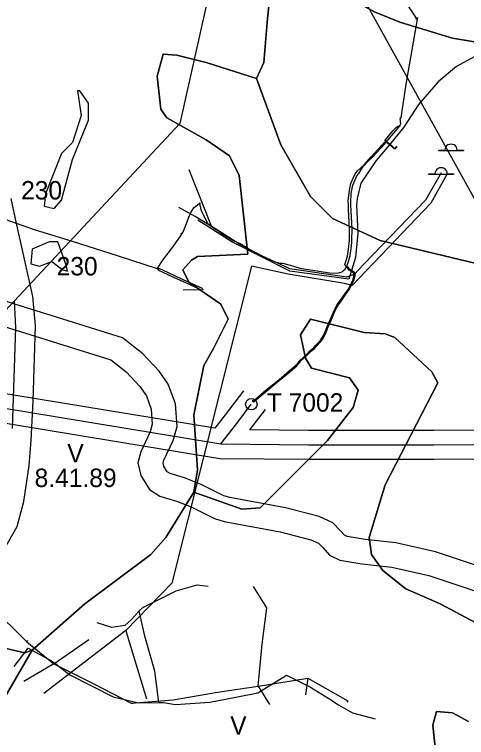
# Model space of a CAD drawing. Extents: x -694504 to -690518, y -983661 to -978958.
# Drawn here: x -691746 to -691377, y -981663 to -981074 of the extents above; entities that cross this region are included whole.
import ezdxf

# ---------------------------------------------------------------- set-up
doc = ezdxf.new("R2010")
doc.units = 0
for name, color, linetype in [('BPEJ', 7, 'Continuous'), ('kabelové a venkovní rozvody telefonu', 7, 'Continuous'), ('lokální biokoridory', 7, 'Continuous'), ('ochranné pásmo dálkového kabelu', 7, 'Continuous'), ('ochranné pásmo radioreleové trasy', 7, 'Continuous'), ('ochranné pásmo silnic', 7, 'Continuous'), ('ochranné pásmo vedení', 7, 'Continuous'), ('trafostanice', 7, 'Continuous'), ('třídy přednosti v ochraně ZP', 7, 'Continuous'), ('vedení NN', 7, 'Continuous'), ('vedení VN 35kV', 7, 'Continuous'), ('vodojem', 7, 'Continuous'), ('vodovodní řad', 7, 'Continuous')]:
    doc.layers.add(name, color=color, linetype=linetype)

msp = doc.modelspace()

# ---------------------------------------------------------------- linework, layer by layer
at = {"layer": 'BPEJ'}
for points in [[(-691323.4, -981103.81), (-691388.4, -981092.81), (-691431.4, -981079.81), (-691451.4, -981071.81), (-691490.4, -981050.81), (-691499.4, -981044.81), (-691533.4, -981020.81), (-691530.4, -980992.81), (-691550.4, -980960.81), (-691589.4, -980933.81), (-691615.4, -980899.81), (-691590.4, -980906.81), (-691536.4, -980918.81), (-691486.4, -980932.81), (-691475.4, -980938.81), (-691401.4, -980969.81), (-691425.4, -980995.81), (-691438.4, -981013.81), (-691451.4, -981026.81), (-691421.4, -981045.81), (-691389.4, -981050.81), (-691376.4, -981048.81)], [(-691533.4, -981020.81), (-691539.4, -981076.81), (-691542.4, -981112.81), (-691548.4, -981125.81), (-691589.4, -981112.81), (-691613.4, -981106.81), (-691624.4, -981105.81), (-691629.4, -981123.81), (-691626.4, -981150.81), (-691621.4, -981157.81), (-691589.4, -981175.81), (-691570.4, -981188.81), (-691562.4, -981204.81), (-691555.4, -981268.81), (-691596.4, -981270.81), (-691601.4, -981273.81), (-691608.4, -981281.81), (-691603.4, -981291.81), (-691577.4, -981309.81), (-691571.4, -981321.81), (-691583.4, -981345.81), (-691591.4, -981359.81), (-691599.4, -981399.81), (-691596.4, -981444.81), (-691599.4, -981462.81), (-691622.4, -981499.81), (-691634.4, -981513.81), (-691688.4, -981553.81), (-691731.4, -981591.81), (-691737.4, -981593.81), (-691763.4, -981587.81)], [(-691363.4, -981277.81), (-691447.4, -981257.81), (-691486.4, -981239.81), (-691504.4, -981221.81), (-691528.4, -981179.81), (-691548.4, -981125.81), (-691542.4, -981112.81), (-691539.4, -981076.81), (-691533.4, -981020.81), (-691499.4, -981044.81), (-691490.4, -981050.81), (-691451.4, -981071.81), (-691431.4, -981079.81), (-691388.4, -981092.81), (-691323.4, -981103.81)], [(-691323.4, -981593.81), (-691398.4, -981553.81), (-691426.4, -981541.81), (-691445.4, -981526.81), (-691454.4, -981513.81), (-691456.4, -981499.81), (-691443.4, -981456.81), (-691400.4, -981373.81), (-691405.4, -981364.81), (-691435.4, -981336.81), (-691443.4, -981333.81), (-691460.4, -981332.81), (-691504.4, -981321.81), (-691512.4, -981334.81), (-691508.4, -981353.81), (-691503.4, -981361.81), (-691472.4, -981369.81), (-691465.4, -981379.81), (-691469.4, -981393.81), (-691490.4, -981420.81), (-691541.4, -981471.81), (-691545.4, -981475.81), (-691560.4, -981476.81), (-691599.4, -981462.81), (-691596.4, -981444.81), (-691599.4, -981399.81), (-691591.4, -981359.81), (-691583.4, -981345.81), (-691571.4, -981321.81), (-691577.4, -981309.81), (-691603.4, -981291.81), (-691608.4, -981281.81), (-691601.4, -981273.81), (-691596.4, -981270.81), (-691555.4, -981268.81), (-691562.4, -981204.81), (-691570.4, -981188.81), (-691589.4, -981175.81), (-691621.4, -981157.81), (-691626.4, -981150.81), (-691629.4, -981123.81), (-691624.4, -981105.81), (-691613.4, -981106.81), (-691589.4, -981112.81), (-691548.4, -981125.81), (-691548.4, -981125.81), (-691528.4, -981179.81), (-691504.4, -981221.81), (-691486.4, -981239.81), (-691447.4, -981257.81), (-691363.4, -981277.81)], [(-691753.4, -981629.81), (-691731.4, -981591.81), (-691688.4, -981553.81), (-691634.4, -981513.81), (-691622.4, -981499.81), (-691599.4, -981462.81), (-691560.4, -981476.81), (-691545.4, -981475.81), (-691541.4, -981471.81), (-691490.4, -981420.81), (-691469.4, -981393.81), (-691465.4, -981379.81), (-691472.4, -981369.81), (-691503.4, -981361.81), (-691508.4, -981353.81), (-691512.4, -981334.81), (-691504.4, -981321.81), (-691460.4, -981332.81), (-691443.4, -981333.81), (-691435.4, -981336.81), (-691405.4, -981364.81), (-691400.4, -981373.81), (-691443.4, -981456.81), (-691456.4, -981499.81), (-691454.4, -981513.81), (-691445.4, -981526.81), (-691426.4, -981541.81), (-691398.4, -981553.81), (-691323.4, -981593.81)], [(-692030.4, -981663.81), (-692015.4, -981623.81), (-692009.4, -981596.81), (-691998.4, -981598.81), (-691992.4, -981605.81), (-691988.4, -981612.81), (-691985.4, -981609.81), (-691948.4, -981586.81), (-691921.4, -981575.81), (-691876.4, -981568.81), (-691866.4, -981564.81), (-691852.4, -981578.81), (-691817.4, -981566.81), (-691796.4, -981572.81), (-691763.4, -981587.81), (-691737.4, -981593.81), (-691731.4, -981591.81), (-691731.4, -981591.81), (-691753.4, -981629.81), (-691759.4, -981656.81), (-691761.4, -981706.81)], [(-691371.4, -982039.81), (-691445.4, -982014.81), (-691447.4, -982011.81), (-691440.4, -982004.81), (-691402.4, -982004.81), (-691441.4, -981972.81), (-691405.4, -981917.81), (-691387.4, -981883.81), (-691381.4, -981854.81), (-691379.4, -981818.81), (-691386.4, -981746.81), (-691402.4, -981673.81), (-691404.4, -981652.81), (-691401.4, -981641.81), (-691388.4, -981642.81), (-691375.4, -981649.81)], [(-691375.4, -981649.81), (-691388.4, -981642.81), (-691401.4, -981641.81), (-691404.4, -981652.81), (-691402.4, -981673.81)]]:
    msp.add_lwpolyline(points, dxfattribs=at)
for points in [[(-691707.4, -981224.81), (-691698.4, -981191.81), (-691685.4, -981159.81), (-691685.4, -981145.81), (-691692.4, -981135.81), (-691694.4, -981135.81), (-691691.4, -981155.81), (-691698.4, -981177.81), (-691707.4, -981186.81), (-691720.4, -981219.81), (-691721.4, -981229.81), (-691713.4, -981231.81), (-691707.4, -981224.81)], [(-691710.4, -981258.81), (-691717.4, -981258.81), (-691731.4, -981264.81), (-691732.4, -981276.81), (-691725.4, -981278.81), (-691715.4, -981274.81), (-691706.4, -981281.81), (-691702.4, -981282.81), (-691703.4, -981278.81), (-691710.4, -981258.81)]]:
    msp.add_lwpolyline(points, close=True, dxfattribs=at)
at = {"layer": 'kabelové a venkovní rozvody telefonu'}
for points in [[(-691367.81, -981106.52), (-691385.07, -981115.89), (-691400.23, -981128.43), (-691416.28, -981146.83), (-691422.12, -981156.15), (-691428.2, -981165.36), (-691441.44, -981181.65), (-691450.78, -981192.73), (-691463.31, -981211.08), (-691466.21, -981223.56), (-691466.79, -981229.06), (-691465.61, -981251.91), (-691467.67, -981271.63), (-691472.94, -981289.31), (-691521.18, -981282.8), (-691568.43, -981259.02), (-691596.27, -981241.13)], [(-691746, -981307.06), (-691744.84, -981328.69), (-691747.77, -981410.96)], [(-691644.15, -981559.69), (-691640.93, -981557.05), (-691613.99, -981543.28), (-691596.77, -981538.34), (-691587.69, -981539.51)], [(-691628.13, -981634.32), (-691631.27, -981608.91), (-691639.46, -981580.2), (-691644.15, -981559.69), (-691650.3, -981566.72), (-691655.86, -981571.7), (-691666.41, -981573.17), (-691678.41, -981569.36)], [(-691746.07, -981605.07), (-691734.68, -981590.08), (-691715.53, -981600.26), (-691711.87, -981603.06), (-691700.59, -981611.68), (-691665.26, -981629.8), (-691644.59, -981634.75), (-691628.13, -981634.32), (-691624.23, -981634.22), (-691614.29, -981635.98), (-691586.26, -981633.94), (-691565.21, -981630.13), (-691547.15, -981626.34), (-691523.85, -981612.18), (-691504.35, -981621.96), (-691489.39, -981631.06), (-691481.49, -981636.33), (-691470.05, -981642.79), (-691451.46, -981647.7)]]:
    msp.add_lwpolyline(points, dxfattribs=at)
at = {"layer": 'lokální biokoridory'}
for points in [[(-691361.64, -981525.13), (-691402.33, -981511.48), (-691434.7, -981504.15), (-691459.73, -981501.42), (-691474.3, -981498.99), (-691476.63, -981497.88), (-691479.73, -981494.4), (-691486.19, -981487.94), (-691497.14, -981482.79), (-691524.8, -981475.78), (-691570.05, -981467.32), (-691575.03, -981465.79), (-691593.52, -981456.55), (-691606.94, -981451.35), (-691618.72, -981447.78), (-691621.09, -981446.25), (-691624.02, -981441.6), (-691624.52, -981439.36), (-691623.84, -981436.81), (-691616.25, -981420.73), (-691613.17, -981409.49), (-691614.36, -981390.9), (-691620.35, -981374.92), (-691627.8, -981364.29), (-691641.06, -981350.05), (-691657.68, -981337.11), (-691834.25, -981281.95)], [(-691838.75, -981301.5), (-691667.11, -981355.12), (-691654.6, -981364.85), (-691643.38, -981376.9), (-691638.19, -981384.31), (-691634.13, -981395.14), (-691633.35, -981407.43), (-691635.08, -981413.77), (-691642.7, -981429.91), (-691645.11, -981438.95), (-691642.78, -981449.34), (-691635.65, -981460.67), (-691627.19, -981466.11), (-691613.46, -981470.27), (-691601.62, -981474.86), (-691582.48, -981484.43), (-691574.83, -981486.77), (-691529.1, -981495.32), (-691503.92, -981501.71), (-691497.86, -981504.56), (-691494.27, -981508.14), (-691488.87, -981514.2), (-691480.36, -981518.25), (-691462.46, -981521.24), (-691438, -981523.91), (-691407.74, -981530.76), (-691369.31, -981543.65)]]:
    msp.add_lwpolyline(points, dxfattribs=at)
at = {"layer": 'ochranné pásmo dálkového kabelu'}
msp.add_lwpolyline([(-691386.18, -980026.89), (-691386.18, -980026.89), (-691386.18, -980026.89), (-691386.18, -980026.89), (-691374.89, -980105.48), (-691346.89, -980518.48), (-691469.89, -980660.48), (-691539.89, -980845.48), (-691610.89, -981162.48), (-691809.89, -981375.48), (-691969.89, -981494.48), (-692021.89, -981584.48), (-692040.89, -981697.48), (-692016.89, -981835.48), (-692032.89, -981838.48)], dxfattribs=at)
at = {"layer": 'ochranné pásmo radioreleové trasy'}
msp.add_line((-692605.8, -978994.48), (-690996.63, -981898.89), dxfattribs=at)
at = {"layer": 'ochranné pásmo silnic'}
msp.add_lwpolyline([(-691753.67, -981508.43), (-691743.55, -981490.93), (-691738.2, -981470.42), (-691733.75, -981441.14), (-691732.14, -981420.54), (-691730.58, -981388.76), (-691728.48, -981326.98), (-691730.72, -981303.42), (-691744.95, -981240.26), (-691748.41, -981223.45)], dxfattribs=at)
at = {"layer": 'ochranné pásmo vedení'}
for points in [[(-691558.97, -981380.3), (-691573.82, -981399.76), (-691582.36, -981410.87), (-691889.01, -981360.42), (-691967.02, -981346.42), (-692032.75, -981335.74), (-692018.07, -981298.31), (-691997.11, -981245.42), (-691974.08, -981189.94), (-691978.27, -981130.33), (-691981.27, -981063.4), (-691984.94, -980999.1), (-691944.3, -980963.87), (-691898.15, -980923.75), (-691865.14, -980893.19), (-691838.56, -980919.95), (-691807.63, -980949.47)], [(-692098.78, -981564.62), (-692085.68, -981520.16), (-692075.66, -981482.06), (-692062.69, -981435.2), (-692049.71, -981390.24), (-692040.57, -981358.27), (-691970.98, -981369.58), (-691892.99, -981383.58), (-691578.35, -981435.35), (-691505.97, -981436.12), (-691403.79, -981436.1), (-691320.85, -981435.75), (-691226.93, -981433.75), (-691115.11, -981434.75), (-691018, -981435.75), (-690919.94, -981434.75), (-690865, -981434.75), (-690798.01, -981434.75), (-690720.4, -981434.84), (-690660.99, -981434.75), (-690632.73, -981444.66)], [(-690632.8, -981419.74), (-690657.01, -981411.25), (-690720.41, -981411.34), (-690797.99, -981411.25), (-690865, -981411.25), (-690920.06, -981411.25), (-691018, -981412.25), (-691114.89, -981411.25), (-691227.07, -981410.25), (-691321.15, -981412.25), (-691403.85, -981412.6), (-691505.85, -981412.62), (-691553.69, -981412.11), (-691541.05, -981395.56)]]:
    msp.add_lwpolyline(points, dxfattribs=at)
at = {"layer": 'trafostanice'}
msp.add_ellipse((-691552.56, -981391.27), major_axis=(0, 4.66), ratio=0.997816, dxfattribs=at)
at = {"layer": 'vedení NN'}
for points in [[(-691417.31, -981077.3), (-691439.8, -981043.48), (-691456.74, -981018.2)], [(-691417.31, -981077.3), (-691421.6, -981102.52), (-691426.4, -981130.32), (-691430.69, -981157.82)], [(-691417.31, -981077.3), (-691418.55, -981077.27)], [(-691416.91, -981076.11), (-691417.31, -981077.3)], [(-691431.03, -981164.2), (-691430.9, -981164.05), (-691431.39, -981163.75), (-691431.13, -981163.51), (-691430.6, -981162.42), (-691430.95, -981161.1), (-691430.99, -981159.89), (-691431.25, -981158.51), (-691430.69, -981157.82)], [(-691474.62, -981278.64), (-691473.15, -981274.79), (-691471.95, -981270.13), (-691470.85, -981262.49), (-691470.63, -981259.56), (-691470.43, -981257.16), (-691470.35, -981248.68), (-691471.18, -981233.69), (-691471.27, -981228.73), (-691471.26, -981226.67), (-691471.08, -981219.48), (-691469.64, -981212.82), (-691466.43, -981205.2), (-691464.97, -981203.09), (-691461.36, -981197.62), (-691457.78, -981193.63), (-691453.47, -981189.48), (-691450.37, -981186.37), (-691446.02, -981181.62), (-691433.19, -981166.75), (-691431.03, -981164.2)], [(-691433.84, -981181.34), (-691433.99, -981181.21), (-691435.31, -981182.66), (-691435.77, -981182.74), (-691437.17, -981181.47), (-691440.95, -981178.46), (-691442.83, -981176.95), (-691442.83, -981176.95), (-691443.42, -981176.56), (-691443.27, -981175.98), (-691441.64, -981174.13), (-691437.12, -981168.46), (-691434.03, -981165.31), (-691433.37, -981164.98), (-691432.1, -981164.47), (-691431.59, -981164.09), (-691431.16, -981164.35), (-691431.03, -981164.2)], [(-691551.47, -981388.22), (-691550.72, -981389.07), (-691548.47, -981387.02), (-691545.16, -981384.03), (-691541.79, -981381.29), (-691534.99, -981375.76), (-691529.71, -981371.27), (-691523.4, -981366.06), (-691515.77, -981359.54), (-691514.17, -981357.86), (-691512.37, -981355.72), (-691507.56, -981351.34), (-691503.91, -981347.58), (-691501.36, -981345.46), (-691500.04, -981343.96), (-691496.15, -981339.79), (-691494.6, -981337.61), (-691493.32, -981335.39), (-691491.83, -981332.27), (-691490.27, -981328.05), (-691487.65, -981322.02), (-691484.47, -981314.61), (-691482.07, -981310.28), (-691479.39, -981306.64), (-691475.7, -981301.33), (-691473, -981297.56), (-691469.42, -981290.21), (-691468.28, -981286.22), (-691468.11, -981284.88), (-691469.01, -981283.87), (-691472.54, -981281.65), (-691473.6, -981280.44), (-691474.82, -981279.26), (-691476.04, -981278.09), (-691476.22, -981277.26), (-691475.18, -981274.12), (-691474.19, -981270.49), (-691473.17, -981264.98), (-691472.56, -981257.71), (-691472.44, -981250.36), (-691472.71, -981242.97), (-691473.33, -981232.48), (-691473.39, -981228.7), (-691473.45, -981225.48), (-691473.02, -981221.27), (-691472.36, -981216.78), (-691471.26, -981211.46), (-691469.59, -981207.01), (-691467.82, -981203.46), (-691465.98, -981201.14), (-691460.6, -981196.2), (-691454.69, -981189.69), (-691449.38, -981183.68), (-691445.55, -981179.61), (-691445.29, -981179.89), (-691445.14, -981179.75)], [(-691433.84, -981181.34), (-691433.69, -981181.47), (-691435.11, -981183.04), (-691435.89, -981183.16), (-691437.43, -981181.77), (-691441.2, -981178.78), (-691443.08, -981177.27), (-691443.08, -981177.27), (-691445.26, -981179.33), (-691444.99, -981179.61), (-691445.14, -981179.75)], [(-691609.81, -981252.02), (-691609.73, -981251.83), (-691608.96, -981252.16), (-691607.98, -981250.4), (-691607.88, -981250.13), (-691604.56, -981241.68), (-691603.51, -981238.88), (-691601.57, -981234.55), (-691600.31, -981232.43), (-691600.13, -981232.14), (-691599.05, -981230.81), (-691595.06, -981227.57), (-691594.57, -981227.13), (-691594.44, -981227.28)], [(-691594.44, -981227.28), (-691594.31, -981227.43), (-691594.86, -981227.95), (-691594.37, -981229.72), (-691593.62, -981232.87), (-691591.33, -981237.76), (-691589.67, -981241.35), (-691588.21, -981243.79), (-691584.35, -981246.84), (-691578.23, -981250.86), (-691576.5, -981252.07), (-691566.82, -981257.95), (-691561.54, -981260.32), (-691546.18, -981269.72), (-691536.97, -981273.45), (-691532.46, -981275.33), (-691531.08, -981276.13), (-691531.05, -981275.87), (-691531.02, -981275.7), (-691530.62, -981275.76)], [(-691763.57, -981237.94), (-691763.49, -981237.76), (-691764.2, -981237.51), (-691763.95, -981236.93), (-691728.83, -981249.2), (-691698.83, -981258.33), (-691661.28, -981270.39), (-691629.29, -981280.71)], [(-691628.75, -981279.62), (-691628.57, -981279.7), (-691625.45, -981275.01), (-691616.08, -981262.49), (-691613.52, -981258.95), (-691610.19, -981254.4), (-691609.15, -981252.52), (-691609.89, -981252.2), (-691609.81, -981252.02)], [(-691530.62, -981275.76), (-691530.22, -981275.82), (-691530.26, -981276.04), (-691530.29, -981276.24), (-691526.91, -981276.27), (-691521.89, -981277.56), (-691521.76, -981277.57), (-691521.76, -981277.57), (-691516.64, -981279.33), (-691511.7, -981280.55), (-691498.83, -981282.64), (-691497.48, -981282.85), (-691488.49, -981284.16), (-691482.16, -981284.53), (-691478.57, -981283.36), (-691477.41, -981282.29), (-691476.06, -981281.05), (-691475.37, -981279.77)], [(-691629.29, -981280.71), (-691628.75, -981279.62)], [(-691629.29, -981280.71), (-691627.46, -981280.65), (-691624.49, -981282.06), (-691615.23, -981286.3), (-691608.95, -981289.21), (-691601.12, -981292.81), (-691592.75, -981296.64), (-691592, -981297.93)], [(-691629.29, -981280.71), (-691628.19, -981282.12), (-691625.23, -981283.46), (-691616.03, -981287.7), (-691610.61, -981290.2), (-691602.8, -981293.79), (-691593.44, -981298.11), (-691608.14, -981298.17)], [(-691551.47, -981388.22), (-691551.78, -981388.48), (-691550.76, -981389.63), (-691550.45, -981389.37), (-691548.2, -981387.32), (-691544.9, -981384.33), (-691541.54, -981381.6), (-691534.73, -981376.07), (-691529.45, -981371.58), (-691523.14, -981366.37), (-691515.49, -981359.83), (-691513.87, -981358.13), (-691512.08, -981356), (-691507.28, -981351.63), (-691503.64, -981347.87), (-691501.08, -981345.75), (-691499.74, -981344.23), (-691495.84, -981340.04), (-691494.26, -981337.83), (-691492.97, -981335.58), (-691491.46, -981332.43), (-691489.9, -981328.2), (-691487.28, -981322.18), (-691484.11, -981314.79), (-691481.73, -981310.5), (-691479.07, -981306.87), (-691475.37, -981301.56), (-691472.66, -981297.77), (-691469.05, -981290.35), (-691467.89, -981286.3), (-691467.69, -981284.75), (-691468.75, -981283.56), (-691472.28, -981281.34), (-691473.31, -981280.16), (-691474.54, -981278.97), (-691474.62, -981278.64)], [(-691551.47, -981388.22), (-691551.18, -981387.97), (-691550.69, -981388.51), (-691548.74, -981386.72), (-691545.42, -981383.73), (-691542.04, -981380.98), (-691535.25, -981375.45), (-691529.97, -981370.96), (-691523.66, -981365.75), (-691516.05, -981359.25), (-691514.47, -981357.59), (-691512.66, -981355.44), (-691507.84, -981351.05), (-691504.18, -981347.29), (-691501.64, -981345.17), (-691500.34, -981343.69), (-691496.46, -981339.54), (-691494.94, -981337.39), (-691493.67, -981335.2), (-691492.2, -981332.11), (-691490.64, -981327.9), (-691488.02, -981321.86), (-691484.83, -981314.43), (-691482.41, -981310.06), (-691479.71, -981306.41), (-691476.03, -981301.1), (-691473.34, -981297.35), (-691469.8, -981290.07), (-691468.67, -981286.14), (-691468.53, -981285.01), (-691469.27, -981284.18), (-691472.8, -981281.96), (-691473.89, -981280.72), (-691475.1, -981279.55), (-691475.37, -981279.77)], [(-691815.54, -981505.69), (-691815.26, -981505.41), (-691815.87, -981504.74), (-691815.48, -981504.34), (-691804.05, -981517.19), (-691789.57, -981531.73), (-691765.19, -981555.79), (-691735.59, -981584.81)], [(-691547.03, -981620.95), (-691543.66, -981586.73), (-691539.99, -981557.06), (-691550.82, -981539.77)], [(-691735.59, -981584.81), (-691734.73, -981583.89)], [(-691735.59, -981584.81), (-691713.59, -981602.96)], [(-691713.59, -981602.96), (-691685.2, -981583.04)], [(-691713.59, -981602.96), (-691738.22, -981617.24)], [(-691713.59, -981602.96), (-691680.95, -981619.03), (-691650.59, -981634.97)], [(-691547.03, -981620.95), (-691506.32, -981614.55)], [(-691506.32, -981614.55), (-691508.26, -981628.19)], [(-691506.32, -981614.55), (-691473.89, -981632.98), (-691474.54, -981634.06)], [(-691650.59, -981634.97), (-691616.31, -981632.04), (-691580.25, -981625.98), (-691547.03, -981620.95)], [(-691547.03, -981620.95), (-691537.66, -981635.96)], [(-691650.59, -981634.97), (-691649.31, -981634.8)]]:
    msp.add_lwpolyline(points, dxfattribs=at)
at = {"layer": 'vedení VN 35kV'}
for points in [[(-692836.19, -981198.9), (-692742.12, -981216.52), (-692657.68, -981232.3), (-692588, -981245), (-692503, -981261), (-692435, -981273), (-692237, -981310), (-692134, -981329), (-692049, -981345), (-691969, -981358), (-691891, -981372), (-691577.33, -981423.61), (-691505.91, -981424.37), (-691403.82, -981424.35), (-691321, -981424), (-691227, -981422), (-691115, -981423), (-691018, -981424), (-690920, -981423), (-690865, -981423), (-690798, -981423), (-690720.41, -981423.09), (-690659, -981423), (-690630.93, -981432.84)], [(-691577.33, -981423.61), (-691564.49, -981406.9), (-691552.56, -981391.27)]]:
    msp.add_lwpolyline(points, dxfattribs=at)
at = {"layer": 'vodojem'}
for p, q in [((-691399.67, -981184.26), (-691394.66, -981184.26)), ((-691399.67, -981184.79), (-691399.67, -981184.26)), ((-691399.67, -981184.79), (-691399.67, -981184.26)), ((-691399.67, -981184.26), (-691394.66, -981184.26)), ((-691379.56, -981184.79), (-691399.67, -981184.79)), ((-691379.56, -981184.79), (-691399.67, -981184.79)), ((-691384.59, -981184.25), (-691379.56, -981184.25)), ((-691384.59, -981184.25), (-691379.56, -981184.25)), ((-691379.56, -981184.25), (-691379.56, -981184.79)), ((-691379.56, -981184.25), (-691379.56, -981184.79)), ((-691407.77, -981203.46), (-691402.77, -981203.46)), ((-691407.77, -981203.99), (-691407.77, -981203.46)), ((-691407.77, -981203.99), (-691407.77, -981203.46)), ((-691407.77, -981203.46), (-691402.77, -981203.46)), ((-691387.67, -981203.99), (-691407.77, -981203.99)), ((-691387.67, -981203.99), (-691407.77, -981203.99)), ((-691392.7, -981203.45), (-691387.67, -981203.45)), ((-691392.7, -981203.45), (-691387.67, -981203.45)), ((-691387.67, -981203.45), (-691387.67, -981203.99)), ((-691387.67, -981203.45), (-691387.67, -981203.99))]:
    msp.add_line(p, q, dxfattribs=at)
for centre in [(-691389.63, -981184.25), (-691389.63, -981184.25), (-691397.74, -981203.45), (-691397.74, -981203.45)]:
    msp.add_ellipse(centre, major_axis=(-5.03, 0), ratio=0.990986, start_param=3.141359, end_param=6.28742, dxfattribs=at)
at = {"layer": 'vodovodní řad'}
for points in [[(-691392.7, -981203.45), (-691406.2, -981227.47), (-691470.26, -981294.4), (-691476.48, -981292.78), (-691522.43, -981285.21), (-691552.3, -981278.7), (-691617.38, -981537.06), (-691654.95, -981575.6), (-691652.98, -981582.15), (-691638.19, -981631.31)], [(-691397.72, -981202.62), (-691410.6, -981224.97), (-691460.41, -981276.9), (-691468.64, -981285.48), (-691474.95, -981287.72), (-691521.08, -981280.88), (-691544.05, -981270.33), (-691562.16, -981260.87), (-691580.19, -981249.28), (-691598.3, -981238.19), (-691611.81, -981230.89)], [(-691585.14, -981246.24), (-691603.16, -981200.33)], [(-691654.95, -981575.6), (-691721.71, -981626.98)]]:
    msp.add_lwpolyline(points, dxfattribs=at)

# ---------------------------------------------------------------- texts
at = {"layer": 'trafostanice'}
msp.add_text('T 7002', height=15, dxfattribs=at).set_placement((-691539.94, -981397.31))
at = {"layer": 'třídy přednosti v ochraně ZP'}
for s, p in [('230', (-691740.35, -981224.37)), ('230', (-691711.37, -981286.27)), ('V', (-691702.65, -981438.73)), ('8.41.89', (-691729.34, -981458.73)), ('V', (-691569.76, -981660.51))]:
    msp.add_text(s, height=15, dxfattribs=at).set_placement(p)

doc.saveas('drawing.dxf')
